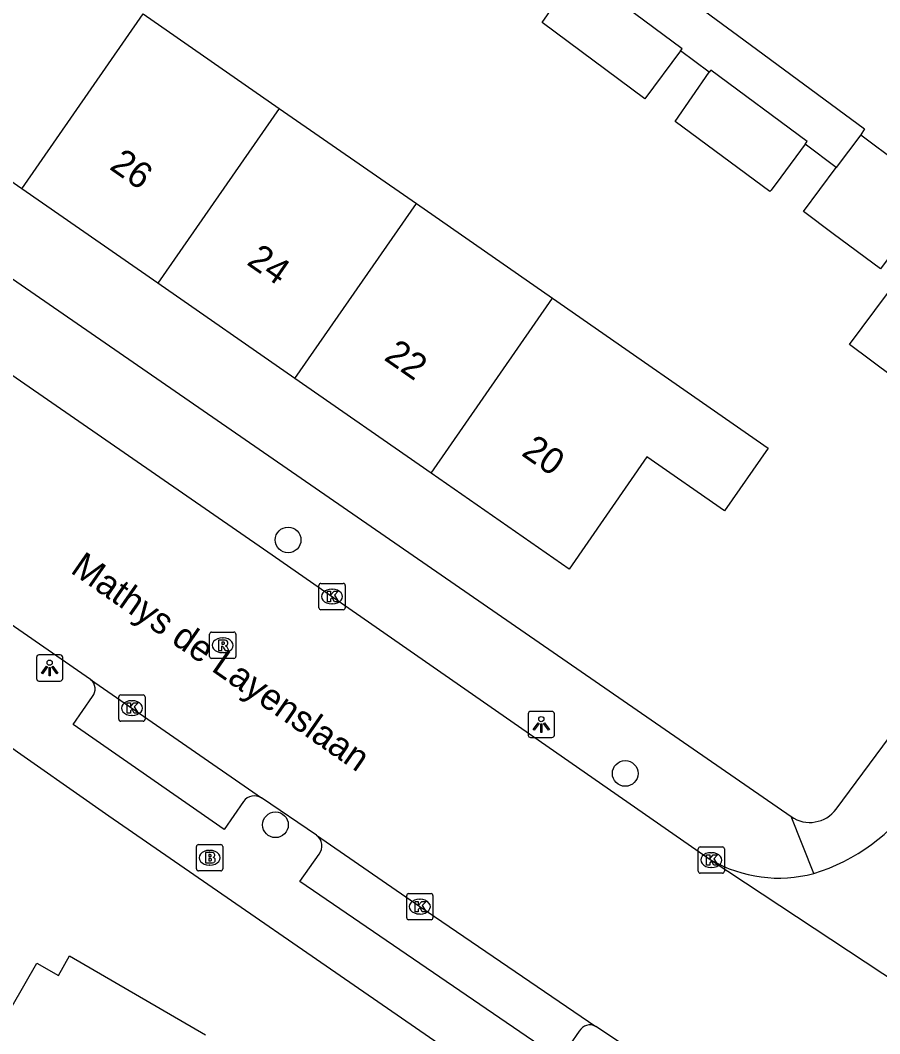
# Model space of a CAD drawing. Extents: x 160026 to 161302, y 384757 to 385701.
# Drawn here: x 160293.94 to 160326.68, y 385134.3 to 385172.88 of the extents above; entities that cross this region are included whole.
import ezdxf

# ---------------------------------------------------------------- set-up
doc = ezdxf.new("R2010")
doc.units = 0
for name, color, linetype in [('IMGEO_Boom', 7, 'Continuous'), ('IMGEO_Brandkraan', 7, 'Continuous'), ('IMGEO_Kolk', 7, 'Continuous'), ('IMGEO_Lichtpunt', 7, 'Continuous'), ('IMGEO_Openbare_ruimte_label', 7, 'Continuous'), ('IMGEO_Pand', 7, 'Continuous'), ('IMGEO_Pand_nummerreeks', 7, 'Continuous'), ('IMGEO_Rijbaan_lokaal_gesloten', 7, 'Continuous'), ('IMGEO_Rijbaan_lokaal_open', 7, 'Continuous'), ('IMGEO_Rioolput', 7, 'Continuous'), ('IMGEO_Voetpad_open', 7, 'Continuous')]:
    doc.layers.add(name, color=color, linetype=linetype)

msp = doc.modelspace()

# ---------------------------------------------------------------- linework, layer by layer
at = {"layer": 'IMGEO_Boom'}
for centre in [(160304.143, 385153.096), (160316.986, 385144.206), (160303.66, 385142.252)]:
    msp.add_circle(centre, 0.489, dxfattribs=at)
at = {"layer": 'IMGEO_Brandkraan'}
for p, q in [((160300.651, 385140.572), (160300.651, 385141.424)), ((160300.726, 385141.498), (160301.578, 385141.498)), ((160301.139, 385141.278), (160301.164, 385141.278)), ((160301.652, 385141.424), (160301.652, 385140.572)), ((160301.578, 385140.498), (160300.726, 385140.498)), ((160301.162, 385140.718), (160301.137, 385140.718))]:
    msp.add_line(p, q, dxfattribs=at)
for points in [[(160300.651, 385140.572), (160300.651, 385141.424)], [(160300.726, 385141.498), (160301.578, 385141.498)], [(160301.652, 385141.424), (160301.652, 385140.572)], [(160300.999, 385141.198), (160300.999, 385140.798), (160301.212, 385140.798)], [(160301.23, 385141.198), (160300.999, 385141.198)], [(160301.178, 385141.117), (160301.124, 385141.117), (160301.124, 385141.041)], [(160301.124, 385141.041), (160301.177, 385141.041)], [(160301.186, 385140.965), (160301.124, 385140.965), (160301.124, 385140.884)], [(160301.124, 385140.884), (160301.186, 385140.884)], [(160301.578, 385140.498), (160300.726, 385140.498)]]:
    msp.add_lwpolyline(points, dxfattribs=at)
for centre, radius, start, end in [((160300.728, 385141.422), 0.0765, 91.552, 178.448), ((160300.728, 385141.422), 0.0765, 91.552, 178.448), ((160301.576, 385141.422), 0.0765, 1.552, 88.448), ((160301.576, 385141.422), 0.0765, 1.552, 88.448), ((160301.179, 385141.079), 0.0379, 267.8285, 90.9355), ((160301.187, 385140.924), 0.0404, 269.8759, 90.5077), ((160301.234, 385141.053), 0.145, 59.4692, 91.5367), ((160301.259, 385141.1), 0.0922, 285.5137, 58.1501), ((160301.264, 385140.908), 0.105, 301.3115, 78.989), ((160300.728, 385140.574), 0.0765, 181.552, 268.448), ((160300.728, 385140.574), 0.0765, 181.552, 268.448), ((160301.218, 385141.049), 0.251, 268.6676, 293.5347), ((160301.576, 385140.574), 0.0765, 271.552, 358.448), ((160301.576, 385140.574), 0.0765, 271.552, 358.448)]:
    msp.add_arc(centre, radius, start, end, dxfattribs=at)
for centre, major_axis, ratio, start_param, end_param in [((160301.138, 385140.998), (-0.387, 0.002), 0.722429, 4.712389, 7.853982), ((160301.163, 385140.998), (-0.39, 0.002), 0.717154, 1.570796, 4.712389)]:
    msp.add_ellipse(centre, major_axis=major_axis, ratio=ratio, start_param=start_param, end_param=end_param, dxfattribs=at)
at = {"layer": 'IMGEO_Kolk'}
for p, q in [((160305.317, 385150.516), (160305.317, 385151.368)), ((160305.392, 385151.442), (160306.244, 385151.442)), ((160306.318, 385151.368), (160306.318, 385150.516)), ((160305.805, 385151.222), (160305.83, 385151.222)), ((160305.828, 385150.662), (160305.803, 385150.662)), ((160306.244, 385150.442), (160305.392, 385150.442)), ((160297.69, 385146.27), (160297.69, 385147.122)), ((160297.765, 385147.196), (160298.617, 385147.196)), ((160298.691, 385147.122), (160298.691, 385146.27)), ((160298.178, 385146.976), (160298.203, 385146.976)), ((160298.201, 385146.416), (160298.176, 385146.416)), ((160298.617, 385146.196), (160297.765, 385146.196)), ((160319.765, 385140.484), (160319.765, 385141.336)), ((160319.84, 385141.41), (160320.692, 385141.41)), ((160320.766, 385141.336), (160320.766, 385140.484)), ((160320.253, 385141.19), (160320.278, 385141.19)), ((160320.276, 385140.63), (160320.251, 385140.63)), ((160320.692, 385140.41), (160319.84, 385140.41)), ((160308.659, 385138.709), (160308.659, 385139.561)), ((160308.734, 385139.635), (160309.586, 385139.635)), ((160309.147, 385139.415), (160309.172, 385139.415)), ((160309.66, 385139.561), (160309.66, 385138.709)), ((160309.586, 385138.635), (160308.734, 385138.635)), ((160309.17, 385138.855), (160309.145, 385138.855))]:
    msp.add_line(p, q, dxfattribs=at)
for points in [[(160305.317, 385150.516), (160305.317, 385151.368)], [(160305.392, 385151.442), (160306.244, 385151.442)], [(160306.318, 385151.368), (160306.318, 385150.516)], [(160305.638, 385151.142), (160305.761, 385151.142), (160305.761, 385150.991), (160305.891, 385151.142), (160306.055, 385151.142), (160305.909, 385150.991), (160306.062, 385150.742), (160305.91, 385150.742), (160305.825, 385150.906), (160305.761, 385150.839), (160305.761, 385150.742), (160305.638, 385150.742), (160305.638, 385151.142)], [(160306.244, 385150.442), (160305.392, 385150.442)], [(160297.69, 385146.27), (160297.69, 385147.122)], [(160297.765, 385147.196), (160298.617, 385147.196)], [(160298.691, 385147.122), (160298.691, 385146.27)], [(160298.011, 385146.896), (160298.134, 385146.896), (160298.134, 385146.745), (160298.264, 385146.896), (160298.428, 385146.896), (160298.282, 385146.745), (160298.435, 385146.496), (160298.283, 385146.496), (160298.198, 385146.66), (160298.134, 385146.593), (160298.134, 385146.496), (160298.011, 385146.496), (160298.011, 385146.896)], [(160298.617, 385146.196), (160297.765, 385146.196)], [(160319.765, 385140.484), (160319.765, 385141.336)], [(160319.84, 385141.41), (160320.692, 385141.41)], [(160320.766, 385141.336), (160320.766, 385140.484)], [(160320.086, 385141.11), (160320.209, 385141.11), (160320.209, 385140.959), (160320.339, 385141.11), (160320.503, 385141.11), (160320.357, 385140.959), (160320.51, 385140.71), (160320.358, 385140.71), (160320.273, 385140.874), (160320.209, 385140.807), (160320.209, 385140.71), (160320.086, 385140.71), (160320.086, 385141.11)], [(160320.692, 385140.41), (160319.84, 385140.41)], [(160308.659, 385138.709), (160308.659, 385139.561)], [(160308.734, 385139.635), (160309.586, 385139.635)], [(160308.98, 385139.335), (160309.103, 385139.335), (160309.103, 385139.184), (160309.233, 385139.335), (160309.397, 385139.335), (160309.251, 385139.184), (160309.404, 385138.935), (160309.252, 385138.935), (160309.167, 385139.099), (160309.103, 385139.032), (160309.103, 385138.935), (160308.98, 385138.935), (160308.98, 385139.335)], [(160309.66, 385139.561), (160309.66, 385138.709)], [(160309.586, 385138.635), (160308.734, 385138.635)]]:
    msp.add_lwpolyline(points, dxfattribs=at)
for centre, start, end in [((160305.394, 385151.366), 91.552, 178.448), ((160305.394, 385151.366), 91.552, 178.448), ((160306.242, 385151.366), 1.552, 88.448), ((160306.242, 385151.366), 1.552, 88.448), ((160305.394, 385150.518), 181.552, 268.448), ((160305.394, 385150.518), 181.552, 268.448), ((160306.242, 385150.518), 271.552, 358.448), ((160306.242, 385150.518), 271.552, 358.448), ((160297.767, 385147.12), 91.552, 178.448), ((160297.767, 385147.12), 91.552, 178.448), ((160298.615, 385147.12), 1.552, 88.448), ((160298.615, 385147.12), 1.552, 88.448), ((160297.767, 385146.272), 181.552, 268.448), ((160297.767, 385146.272), 181.552, 268.448), ((160298.615, 385146.272), 271.552, 358.448), ((160298.615, 385146.272), 271.552, 358.448), ((160319.842, 385141.334), 91.552, 178.448), ((160319.842, 385141.334), 91.552, 178.448), ((160320.69, 385141.334), 1.552, 88.448), ((160320.69, 385141.334), 1.552, 88.448), ((160319.842, 385140.486), 181.552, 268.448), ((160319.842, 385140.486), 181.552, 268.448), ((160320.69, 385140.486), 271.552, 358.448), ((160320.69, 385140.486), 271.552, 358.448), ((160308.736, 385139.559), 91.552, 178.448), ((160308.736, 385139.559), 91.552, 178.448), ((160309.584, 385139.559), 1.552, 88.448), ((160309.584, 385139.559), 1.552, 88.448), ((160308.736, 385138.711), 181.552, 268.448), ((160308.736, 385138.711), 181.552, 268.448), ((160309.584, 385138.711), 271.552, 358.448), ((160309.584, 385138.711), 271.552, 358.448)]:
    msp.add_arc(centre, 0.0765, start, end, dxfattribs=at)
for centre, major_axis, ratio, start_param, end_param in [((160305.804, 385150.942), (-0.387, 0.002), 0.722429, 4.712389, 7.853982), ((160305.829, 385150.942), (-0.39, 0.002), 0.717154, 1.570796, 4.712389), ((160298.177, 385146.696), (-0.387, 0.002), 0.722429, 4.712389, 7.853982), ((160298.202, 385146.696), (-0.39, 0.002), 0.717154, 1.570796, 4.712389), ((160320.252, 385140.91), (-0.387, 0.002), 0.722429, 4.712389, 7.853982), ((160320.277, 385140.91), (-0.39, 0.002), 0.717154, 1.570796, 4.712389), ((160309.146, 385139.135), (-0.387, 0.002), 0.722429, 4.712389, 7.853982), ((160309.171, 385139.135), (-0.39, 0.002), 0.717154, 1.570796, 4.712389)]:
    msp.add_ellipse(centre, major_axis=major_axis, ratio=ratio, start_param=start_param, end_param=end_param, dxfattribs=at)
at = {"layer": 'IMGEO_Lichtpunt'}
for p, q in [((160294.557, 385148.627), (160294.557, 385147.82)), ((160294.557, 385148.627), (160294.557, 385147.82)), ((160295.459, 385148.722), (160294.651, 385148.722)), ((160295.459, 385148.722), (160294.651, 385148.722)), ((160295.553, 385147.82), (160295.553, 385148.627)), ((160295.553, 385147.82), (160295.553, 385148.627)), ((160294.651, 385147.726), (160295.459, 385147.726)), ((160294.651, 385147.726), (160295.459, 385147.726)), ((160313.289, 385146.476), (160313.289, 385145.669)), ((160313.289, 385146.476), (160313.289, 385145.669)), ((160314.191, 385146.571), (160313.383, 385146.571)), ((160314.191, 385146.571), (160313.383, 385146.571)), ((160314.285, 385145.669), (160314.285, 385146.476)), ((160314.285, 385145.669), (160314.285, 385146.476)), ((160313.383, 385145.575), (160314.191, 385145.575)), ((160313.383, 385145.575), (160314.191, 385145.575))]:
    msp.add_line(p, q, dxfattribs=at)
for points in [[(160294.931, 385148.291), (160294.97, 385148.263), (160294.782, 385148.001), (160294.744, 385148.028), (160294.931, 385148.291)], [(160295.033, 385148.243), (160295.08, 385148.243), (160295.08, 385147.921), (160295.033, 385147.921), (160295.033, 385148.243)], [(160295.143, 385148.263), (160295.181, 385148.29), (160295.368, 385148.028), (160295.329, 385148), (160295.143, 385148.263)], [(160313.663, 385146.14), (160313.702, 385146.112), (160313.514, 385145.85), (160313.476, 385145.877), (160313.663, 385146.14)], [(160313.765, 385146.092), (160313.812, 385146.092), (160313.812, 385145.77), (160313.765, 385145.77), (160313.765, 385146.092)], [(160313.875, 385146.112), (160313.913, 385146.139), (160314.1, 385145.877), (160314.061, 385145.849), (160313.875, 385146.112)]]:
    msp.add_lwpolyline(points, dxfattribs=at)
for centre in [(160295.056, 385148.425), (160313.788, 385146.274)]:
    msp.add_circle(centre, 0.0994, dxfattribs=at)
for centre, start, end in [((160294.651, 385148.627), 90, 180), ((160294.651, 385148.627), 90, 180), ((160295.459, 385148.627), 0, 90), ((160295.459, 385148.627), 0, 90), ((160294.651, 385147.82), 180, 270), ((160294.651, 385147.82), 180, 270), ((160295.459, 385147.82), 270, 0), ((160295.459, 385147.82), 270, 360), ((160313.383, 385146.476), 90, 180), ((160313.383, 385146.476), 90, 180), ((160314.191, 385146.476), 0, 90), ((160314.191, 385146.476), 0, 90), ((160313.383, 385145.669), 180, 270), ((160313.383, 385145.669), 180, 270), ((160314.191, 385145.669), 270, 0), ((160314.191, 385145.669), 270, 360)]:
    msp.add_arc(centre, 0.0946, start, end, dxfattribs=at)
at = {"layer": 'IMGEO_Pand'}
for points in [[(160319.097, 385171.721), (160317.738, 385169.888), (160313.817, 385172.796), (160315.134, 385174.693)], [(160319.097, 385171.721), (160319.156, 385171.8), (160315.176, 385174.753), (160315.134, 385174.693)], [(160293.991, 385166.469), (160298.616, 385173.131)], [(160298.616, 385173.131), (160303.803, 385169.53)], [(160323.838, 385168.165), (160323.916, 385168.27), (160320.249, 385170.989), (160320.189, 385170.902)], [(160323.838, 385168.165), (160322.909, 385166.913), (160322.54, 385166.415), (160322.497, 385166.358), (160318.891, 385169.033), (160320.189, 385170.902)], [(160293.991, 385166.469), (160288.691, 385170.149)], [(160303.803, 385169.53), (160299.178, 385162.868)], [(160303.803, 385169.53), (160309.029, 385165.901)], [(160325.956, 385168.527), (160328.889, 385166.338), (160326.706, 385163.414), (160324.91, 385164.754), (160323.773, 385165.603), (160325.023, 385167.277)], [(160325.956, 385168.527), (160325.023, 385167.277)], [(160299.178, 385162.868), (160293.991, 385166.469)], [(160304.403, 385159.239), (160309.029, 385165.901)], [(160309.029, 385165.901), (160314.216, 385162.299)], [(160335.947, 385160.832), (160332.077, 385155.647), (160325.526, 385160.537), (160329.397, 385165.722)], [(160304.403, 385159.239), (160299.178, 385162.868)], [(160314.216, 385162.299), (160322.429, 385156.597), (160320.768, 385154.206), (160317.81, 385156.259), (160314.845, 385151.989), (160309.591, 385155.637)], [(160309.591, 385155.637), (160314.216, 385162.299)], [(160309.591, 385155.637), (160304.403, 385159.239)], [(160296.428, 385126.282), (160291.497, 385129.134), (160293.724, 385132.985), (160292.625, 385133.621), (160294.575, 385136.985), (160295.388, 385136.515), (160295.818, 385137.258), (160300.999, 385134.259)]]:
    msp.add_lwpolyline(points, dxfattribs=at)
at = {"layer": 'IMGEO_Rijbaan_lokaal_gesloten'}
for points in [[(160292.906, 385159.87), (160303.373, 385152.644), (160320.265, 385140.909)], [(160296.619, 385147.784), (160289.202, 385152.911), (160288.457, 385153.426)], [(160296.619, 385147.784), (160303.129, 385143.274)], [(160305.222, 385141.852), (160303.129, 385143.274)], [(160305.222, 385141.852), (160309.156, 385139.136), (160315.869, 385134.573)], [(160320.265, 385140.909), (160333.972, 385131.862)], [(160318.091, 385133.105), (160315.869, 385134.573)]]:
    msp.add_lwpolyline(points, dxfattribs=at)
at = {"layer": 'IMGEO_Rijbaan_lokaal_open'}
for centre, radius, start, end in [((160322.03, 385147.401), 7.323, 286.9587, 325.691), ((160322.84, 385145.398), 5.175, 240.1631, 284.8535)]:
    msp.add_arc(centre, radius, start, end, dxfattribs=at)
at = {"layer": 'IMGEO_Rioolput'}
for p, q in [((160301.151, 385148.66), (160301.151, 385149.512)), ((160301.226, 385149.586), (160302.078, 385149.586)), ((160302.152, 385149.512), (160302.152, 385148.66)), ((160301.639, 385149.366), (160301.664, 385149.366)), ((160301.662, 385148.806), (160301.637, 385148.806)), ((160302.078, 385148.586), (160301.226, 385148.586))]:
    msp.add_line(p, q, dxfattribs=at)
for points in [[(160301.151, 385148.66), (160301.151, 385149.512)], [(160301.226, 385149.586), (160302.078, 385149.586)], [(160302.152, 385149.512), (160302.152, 385148.66)], [(160301.74, 385149.284), (160301.488, 385149.286), (160301.488, 385148.886)], [(160301.488, 385148.886), (160301.612, 385148.886), (160301.612, 385149.048), (160301.623, 385149.048)], [(160301.666, 385149.205), (160301.612, 385149.205), (160301.612, 385149.124)], [(160301.612, 385149.124), (160301.664, 385149.124)], [(160301.67, 385149.019), (160301.741, 385148.886), (160301.881, 385148.886), (160301.816, 385149.012)], [(160302.078, 385148.586), (160301.226, 385148.586)]]:
    msp.add_lwpolyline(points, dxfattribs=at)
for centre, radius, start, end in [((160301.228, 385149.51), 0.0765, 91.552, 178.448), ((160301.228, 385149.51), 0.0765, 91.552, 178.448), ((160302.076, 385149.51), 0.0765, 1.552, 88.448), ((160302.076, 385149.51), 0.0765, 1.552, 88.448), ((160301.622, 385148.995), 0.0533, 26.0293, 88.6989), ((160301.648, 385149.313), 0.19, 274.7715, 282.9687), ((160301.672, 385149.109), 0.0964, 77.0061, 93.1865), ((160301.686, 385149.166), 0.0378, 276.6634, 79.6772), ((160301.739, 385149.174), 0.109, 350.3612, 89.416), ((160301.737, 385149.174), 0.112, 277.5842, 350.9817), ((160301.721, 385148.959), 0.108, 29.5134, 73.7905), ((160301.228, 385148.662), 0.0765, 181.552, 268.448), ((160301.228, 385148.662), 0.0765, 181.552, 268.448), ((160302.076, 385148.662), 0.0765, 271.552, 358.448), ((160302.076, 385148.662), 0.0765, 271.552, 358.448)]:
    msp.add_arc(centre, radius, start, end, dxfattribs=at)
for centre, major_axis, ratio, start_param, end_param in [((160301.638, 385149.086), (-0.387, 0.002), 0.722429, 4.712389, 7.853982), ((160301.663, 385149.086), (-0.39, 0.002), 0.717154, 1.570796, 4.712389)]:
    msp.add_ellipse(centre, major_axis=major_axis, ratio=ratio, start_param=start_param, end_param=end_param, dxfattribs=at)
at = {"layer": 'IMGEO_Voetpad_open'}
for points in [[(160325.028, 385142.851), (160374.618, 385209.767)], [(160323.243, 385179.85), (160318.925, 385174.07), (160318.959, 385174.023), (160321.501, 385172.139), (160326.107, 385168.748), (160325.956, 385168.527)], [(160320.189, 385170.902), (160319.097, 385171.721)], [(160325.023, 385167.277), (160323.838, 385168.165)], [(160287.026, 385167.6), (160323.304, 385142.564)], [(160302.442, 385143.135), (160301.712, 385142.068), (160295.951, 385146.065), (160296.688, 385147.131)], [(160349.593, 385108.411), (160338.466, 385115.299), (160331.075, 385119.978), (160323.23, 385125.041), (160316.405, 385129.52), (160309.902, 385133.903), (160297.312, 385142.585), (160293.095, 385145.525)], [(160324.166, 385140.396), (160323.304, 385142.564)], [(160315.237, 385134.396), (160314.5, 385133.329), (160304.585, 385140.093), (160305.328, 385141.131)]]:
    msp.add_lwpolyline(points, dxfattribs=at)
for centre, radius, start, end in [((160296.317, 385147.422), 0.471, 321.871, 50.1927), ((160302.856, 385142.858), 0.498, 56.6683, 146.2081), ((160324.018, 385143.599), 1.257, 235.4256, 323.4775), ((160304.92, 385141.439), 0.511, 322.8979, 53.8293), ((160315.642, 385134.168), 0.465, 60.7304, 150.5608)]:
    msp.add_arc(centre, radius, start, end, dxfattribs=at)

# ---------------------------------------------------------------- texts
at = {"layer": 'IMGEO_Openbare_ruimte_label'}
msp.add_text('Mathys de Layenslaan', height=1, rotation=325.1816, dxfattribs=at).set_placement((160295.808, 385151.876))
at = {"layer": 'IMGEO_Pand_nummerreeks'}
for s, p in [('26', (160297.295, 385167.242)), ('24', (160302.526, 385163.61)), ('22', (160307.755, 385159.98)), ('20', (160312.991, 385156.344))]:
    msp.add_text(s, height=1, rotation=325.2259, dxfattribs=at).set_placement(p)

doc.saveas('drawing.dxf')
